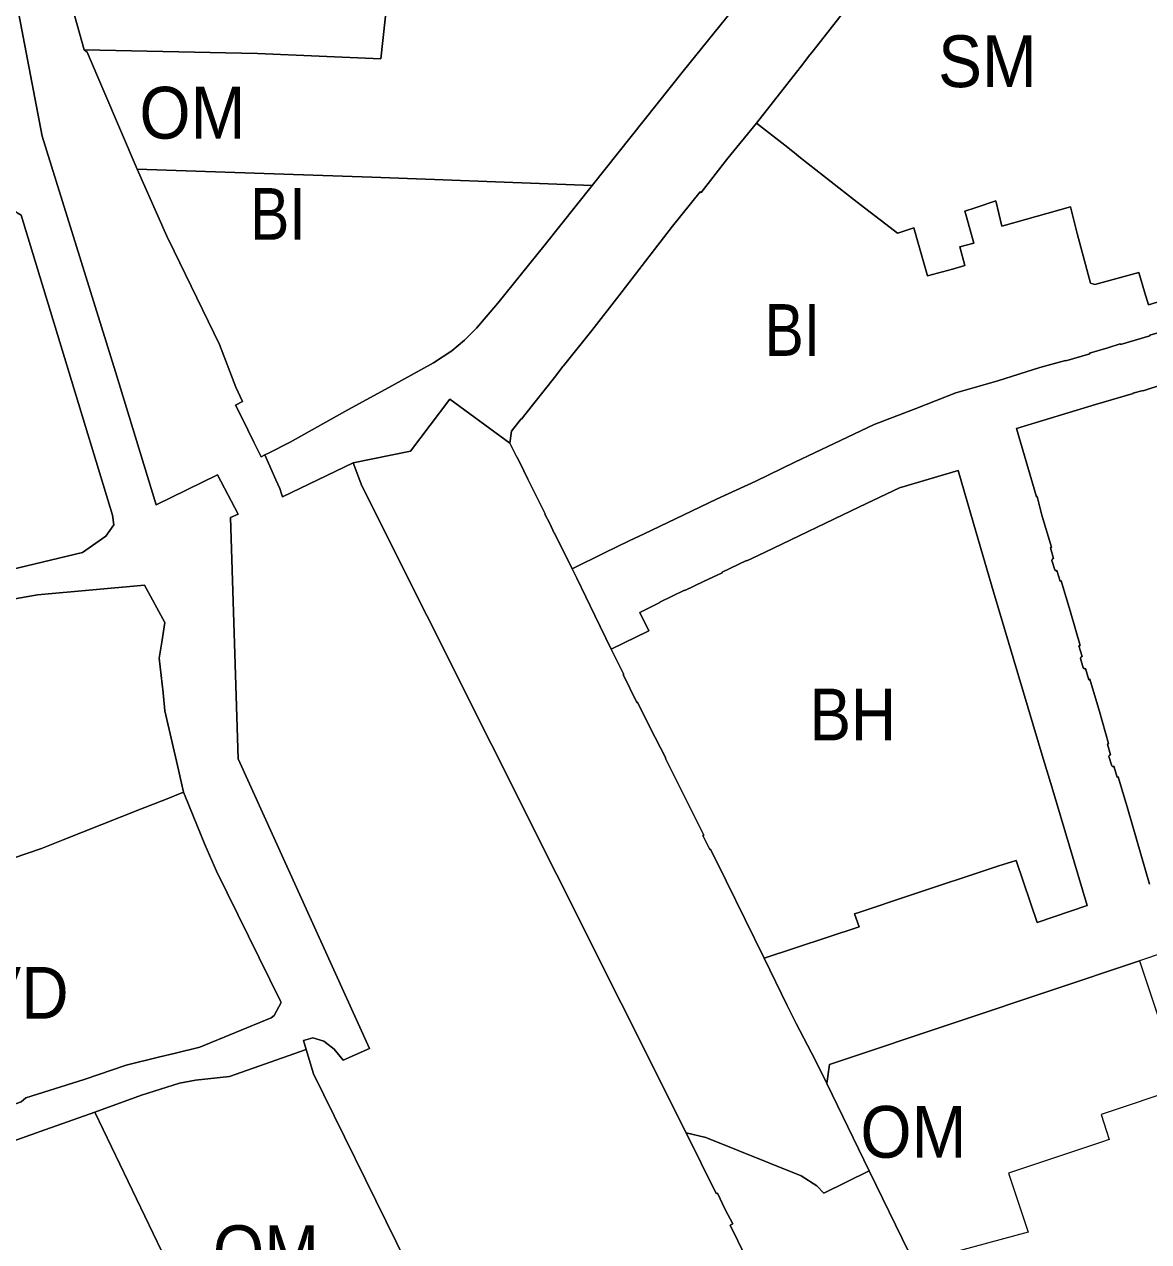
# Model space of a CAD drawing. Extents: x -650451 to -642268, y -1075216 to -1066610.
# Drawn here: x -647868.5 to -647608.2, y -1070794.3 to -1070512.4 of the extents above; entities that cross this region are included whole.
import ezdxf

# ---------------------------------------------------------------- set-up
doc = ezdxf.new("R2010")
doc.units = 0
doc.header["$LTSCALE"] = 4.8
for name, color, linetype, lineweight in [('1', 7, 'Continuous', 13), ('11', 7, 'Continuous', 13), ('12', 7, 'Continuous', 13), ('15', 7, 'Continuous', 13), ('18', 7, 'Continuous', 13), ('2', 7, 'Continuous', 13), ('24', 7, 'Continuous', 13), ('25', 7, 'Continuous', 13), ('35', 7, 'Continuous', 13)]:
    doc.layers.add(name, color=color, linetype=linetype, lineweight=lineweight)
doc.layers.add('62', color=7, linetype='Continuous')

msp = doc.modelspace()

# ---------------------------------------------------------------- linework, layer by layer
at = {"layer": '1'}
for points in [[(-647607.96, -1070711.55), (-647612.98, -1070694.17), (-647615.21, -1070686.65), (-647615.48, -1070686.75), (-647616.22, -1070684.23), (-647616.47, -1070684.33), (-647616.72, -1070684.14), (-647617.37, -1070681.97), (-647617.24, -1070681.65), (-647617.01, -1070681.56), (-647617.73, -1070679.09), (-647617.45, -1070678.98), (-647619.6, -1070671.54), (-647621.78, -1070664.08), (-647622.06, -1070664.18), (-647622.83, -1070661.6), (-647623.03, -1070661.67), (-647623.36, -1070661.41), (-647623.94, -1070659.3), (-647623.84, -1070658.92), (-647623.61, -1070658.84), (-647624.32, -1070656.37), (-647624.04, -1070656.27), (-647626.19, -1070648.79), (-647628.41, -1070641.25), (-647628.67, -1070641.34), (-647629.41, -1070638.87), (-647629.59, -1070638.94), (-647629.93, -1070638.72), (-647630.57, -1070636.58), (-647630.47, -1070636.18), (-647630.25, -1070636.1), (-647630.93, -1070633.62), (-647630.65, -1070633.51), (-647632.89, -1070626.04), (-647633.98, -1070621.78), (-647634.12, -1070621.83), (-647638.76, -1070605.98), (-647620.49, -1070600.48), (-647611.81, -1070597.91), (-647611.83, -1070597.85), (-647609.48, -1070597.18), (-647609.46, -1070597.25), (-647604.74, -1070595.77)], [(-647732.61, -1070657.08), (-647723.91, -1070652.88), (-647725.98, -1070648.59), (-647721.35, -1070646.32), (-647721.4, -1070646.19), (-647715.68, -1070643.41), (-647715.62, -1070643.56), (-647711.25, -1070641.47), (-647706.92, -1070639.43), (-647706.97, -1070639.28), (-647701.31, -1070636.54), (-647701.26, -1070636.68), (-647696.95, -1070634.64), (-647675.17, -1070624.15), (-647665.9, -1070619.71), (-647652.31, -1070615.72), (-647648.1, -1070630.11), (-647644.14, -1070643.84), (-647632.63, -1070682.45), (-647630.62, -1070688.97), (-647622.42, -1070716.46), (-647633.97, -1070720.39), (-647637.16, -1070711.08), (-647638.89, -1070706.02), (-647642.89, -1070707.32), (-647663.76, -1070714.27), (-647675.08, -1070718.03), (-647676.32, -1070718.44), (-647675.18, -1070721.4), (-647697.19, -1070728.71)], [(-647697.19, -1070728.71), (-647706.03, -1070710.73), (-647709.63, -1070703.43), (-647709.81, -1070703.52), (-647711.41, -1070700.27), (-647711.22, -1070700.17), (-647714.83, -1070692.9), (-647718.4, -1070685.67), (-647718.46, -1070685.698), (-647720.094, -1070682.395), (-647720.01, -1070682.36), (-647723.69, -1070675.2), (-647726.54, -1070669.36), (-647726.67, -1070669.43), (-647729.88, -1070663.01), (-647729.74, -1070662.95), (-647732.61, -1070657.08)], [(-647940.38, -1070810.06), (-647941.01, -1070809.16), (-647923.51, -1070797.95), (-647906.13, -1070787.1), (-647898.99, -1070783.35), (-647885.65, -1070776.94), (-647883.78, -1070776.11), (-647878.36, -1070773.89), (-647871.54, -1070771.23), (-647865.7, -1070769.15), (-647864.85, -1070768.85), (-647852.16, -1070764.35)], [(-647852.16, -1070764.35), (-647832.89, -1070804.46), (-647831.15, -1070808.09), (-647815.42, -1070840.8), (-647815.09, -1070841.49)]]:
    msp.add_lwpolyline(points, dxfattribs=at)
at = {"layer": '11'}
msp.add_lwpolyline([(-647879.89, -1070513.91), (-647874.57, -1070543.74), (-647874.57, -1070544.88), (-647875.18, -1070545.86), (-647875.88, -1070546.28), (-647875.79, -1070546.93), (-647875.64, -1070547.77), (-647874.97, -1070551.71), (-647874.48, -1070554.33), (-647872.39, -1070554.51), (-647871.15, -1070555.05), (-647870.17, -1070556.03), (-647869.25, -1070556.63), (-647848.14, -1070626.09), (-647847.8, -1070628.31), (-647849.67, -1070630.94), (-647855.03, -1070634.7), (-647869.87, -1070638.25), (-647907.21, -1070647.84), (-647941.33, -1070659.67), (-647955.81, -1070667.9), (-647961.11, -1070670.91)], dxfattribs=at)
at = {"layer": '12'}
for points in [[(-647854.68, -1070518.29), (-647814.55, -1070519.13), (-647785.99, -1070520.38), (-647781.43, -1070478.65)], [(-647781.43, -1070478.65), (-647696.44, -1070487.29), (-647695.82, -1070490.27), (-647694.91, -1070492.48), (-647693.13, -1070494.91), (-647715.98, -1070523.28), (-647737.05, -1070549.71)], [(-647842.39, -1070545.96), (-647853.97, -1070518.82), (-647854.68, -1070518.29)], [(-647737.05, -1070549.71), (-647757.4, -1070548.94), (-647773.54, -1070548.32), (-647788.08, -1070547.77), (-647842.39, -1070545.96)], [(-647682.67, -1070757.67), (-647682.08, -1070753.29), (-647651.82, -1070743.17), (-647610.33, -1070729.281)], [(-647610.33, -1070729.281), (-647600.53, -1070758.65), (-647619.2, -1070764.85), (-647617.36, -1070770.69), (-647619.12, -1070771.28), (-647640.66, -1070778.47), (-647636.12, -1070792.13), (-647654.89, -1070797.23), (-647662.26, -1070799.23)], [(-647852.16, -1070764.35), (-647841.37, -1070760.42), (-647832.6, -1070757.6), (-647828.92, -1070756.92), (-647821.05, -1070756.07), (-647803.27, -1070749.84)], [(-647803.27, -1070749.84), (-647801.54, -1070755.44), (-647782.32, -1070794.55), (-647764.84, -1070830.47), (-647765.72, -1070830.64)], [(-647662.26, -1070799.23), (-647663.71, -1070796.77), (-647672.865, -1070777.891), (-647682.67, -1070757.67)], [(-647815.09, -1070841.49), (-647815.42, -1070840.8), (-647831.15, -1070808.09), (-647832.89, -1070804.46), (-647852.16, -1070764.35)]]:
    msp.add_lwpolyline(points, dxfattribs=at)
at = {"layer": '15'}
for points in [[(-647884.92, -1070338.99), (-647886.21, -1070365.54), (-647887.07, -1070416.41), (-647878.96, -1070462.33), (-647864.39, -1070538.27), (-647847.43, -1070592.87), (-647838.01, -1070623.65), (-647823.823, -1070616.697), (-647819.04, -1070625.82), (-647820.78, -1070626.64), (-647818.97, -1070682.49), (-647788.61, -1070749.59), (-647794.72, -1070752.32), (-647796.81, -1070749.77), (-647799.17, -1070747.87), (-647801.72, -1070747.13), (-647803.86, -1070747.73), (-647803.27, -1070749.84)], [(-647622.98, -1070439.01), (-647623.27, -1070440.39), (-647624.25, -1070440.21), (-647627.38, -1070444.2), (-647627.26, -1070444.3), (-647636.05, -1070455.39), (-647636.18, -1070455.29), (-647639.17, -1070459.21), (-647641.31, -1070461.98), (-647654.26, -1070478.61), (-647664.91, -1070491.95), (-647674.88, -1070504.49), (-647685.86, -1070518.5), (-647686.94, -1070519.87), (-647688.05, -1070521.29), (-647699, -1070535.25)], [(-647737.05, -1070549.71), (-647715.98, -1070523.28), (-647693.13, -1070494.91), (-647694.91, -1070492.48), (-647695.82, -1070490.27), (-647696.44, -1070487.29), (-647781.43, -1070478.65)], [(-647961.11, -1070670.91), (-647955.81, -1070667.9), (-647941.33, -1070659.67), (-647907.21, -1070647.84), (-647869.87, -1070638.25), (-647855.03, -1070634.7), (-647849.67, -1070630.94), (-647847.8, -1070628.31), (-647848.14, -1070626.09), (-647869.25, -1070556.63), (-647870.17, -1070556.03), (-647871.15, -1070555.05), (-647872.39, -1070554.51), (-647874.48, -1070554.33), (-647874.97, -1070551.71), (-647875.64, -1070547.77), (-647875.79, -1070546.93), (-647875.88, -1070546.28), (-647875.18, -1070545.86), (-647874.57, -1070544.88), (-647874.57, -1070543.74), (-647879.89, -1070513.91)], [(-647699, -1070535.25), (-647705.6, -1070543.36), (-647711.81, -1070551.37), (-647712, -1070551.21), (-647718.41, -1070559.17), (-647724.69, -1070567.22), (-647730.85, -1070575.29), (-647737.13, -1070583.31), (-647743.65, -1070591.47), (-647743.8, -1070591.67), (-647745.76, -1070594.16), (-647752.62, -1070602.85), (-647753.39, -1070603.81), (-647753.47, -1070603.74), (-647755.74, -1070606.59), (-647756.13, -1070609.41)], [(-647812.82, -1070612.11), (-647812, -1070611.69), (-647807, -1070609.17), (-647794.31, -1070602.04), (-647783.46, -1070596.13), (-647773.75, -1070590.81), (-647769.52, -1070587.99), (-647766.59, -1070585.58), (-647763.83, -1070582.8), (-647758.9, -1070576.94), (-647747.95, -1070563.36), (-647737.05, -1070549.71)], [(-647741.7, -1070638.5), (-647734.17, -1070634.77), (-647728.44, -1070632.04), (-647725.01, -1070630.41), (-647717.77, -1070626.96), (-647708.23, -1070622.36), (-647699.17, -1070618.19), (-647690.11, -1070613.79), (-647680.98, -1070609.51), (-647671.77, -1070605.06), (-647662.28, -1070601.45), (-647652.86, -1070597.72), (-647643.11, -1070594.93), (-647633.4, -1070591.9), (-647627.42, -1070590.22), (-647627.38, -1070590.33), (-647621.83, -1070588.68), (-647621.89, -1070588.54), (-647617.66, -1070587.29), (-647614.79, -1070586.43), (-647614.73, -1070586.57), (-647607.88, -1070584.57), (-647607.93, -1070584.42), (-647601.55, -1070582.5)], [(-647604.74, -1070595.77), (-647609.46, -1070597.25), (-647609.48, -1070597.18), (-647611.83, -1070597.85), (-647611.81, -1070597.91), (-647620.49, -1070600.48), (-647638.76, -1070605.98), (-647634.12, -1070621.83), (-647633.98, -1070621.78), (-647632.89, -1070626.04), (-647630.65, -1070633.51), (-647630.93, -1070633.62), (-647630.25, -1070636.1), (-647630.47, -1070636.18), (-647630.57, -1070636.58), (-647629.93, -1070638.72), (-647629.59, -1070638.94), (-647629.41, -1070638.87), (-647628.67, -1070641.34), (-647628.41, -1070641.25), (-647626.19, -1070648.79), (-647624.04, -1070656.27), (-647624.32, -1070656.37), (-647623.61, -1070658.84), (-647623.84, -1070658.92), (-647623.94, -1070659.3), (-647623.36, -1070661.41), (-647623.03, -1070661.67), (-647622.83, -1070661.6), (-647622.06, -1070664.18), (-647621.78, -1070664.08), (-647619.6, -1070671.54), (-647617.45, -1070678.98), (-647617.73, -1070679.09), (-647617.01, -1070681.56), (-647617.24, -1070681.65), (-647617.37, -1070681.97), (-647616.72, -1070684.14), (-647616.47, -1070684.33), (-647616.22, -1070684.23), (-647615.48, -1070686.75), (-647615.21, -1070686.65), (-647612.98, -1070694.17), (-647607.96, -1070711.55)], [(-647756.13, -1070609.41), (-647769.961, -1070599.197), (-647779.08, -1070611.27), (-647792.4, -1070613.99)], [(-647792.4, -1070613.99), (-647808.77, -1070621.81), (-647808.99, -1070621.12), (-647809.39, -1070619.89), (-647810.28, -1070617.88), (-647812.82, -1070612.11)], [(-647697.19, -1070728.71), (-647675.18, -1070721.4), (-647676.32, -1070718.44), (-647675.08, -1070718.03), (-647663.76, -1070714.27), (-647642.89, -1070707.32), (-647638.89, -1070706.02), (-647637.16, -1070711.08), (-647633.97, -1070720.39), (-647622.42, -1070716.46), (-647630.62, -1070688.97), (-647632.63, -1070682.45), (-647644.14, -1070643.84), (-647648.1, -1070630.11), (-647652.31, -1070615.72), (-647665.9, -1070619.71), (-647675.17, -1070624.15), (-647696.95, -1070634.64), (-647701.26, -1070636.68), (-647701.31, -1070636.54), (-647706.97, -1070639.28), (-647706.92, -1070639.43), (-647711.25, -1070641.47), (-647715.62, -1070643.56), (-647715.68, -1070643.41), (-647721.4, -1070646.19), (-647721.35, -1070646.32), (-647725.98, -1070648.59), (-647723.91, -1070652.88), (-647732.61, -1070657.08)], [(-647732.61, -1070657.08), (-647736.4, -1070649.31), (-647740.59, -1070640.7), (-647741.7, -1070638.5)], [(-647831.69, -1070690.25), (-647832.86, -1070685.08), (-647835.96, -1070671.43), (-647836.41, -1070667.24), (-647837.27, -1070659.18), (-647836.7, -1070655.5), (-647835.98, -1070650.97), (-647840.71, -1070642.28), (-647865.49, -1070644.56), (-647897.91, -1070650.27), (-647905.7, -1070652.72), (-647914.94, -1070655.62), (-647928.03, -1070660.74), (-647939.82, -1070666.19), (-647938.2, -1070670.05)], [(-647925.06, -1070789.71), (-647914.43, -1070782.61), (-647894.71, -1070772.31), (-647886.51, -1070768.03), (-647869.29, -1070761.92), (-647868.14, -1070761.03), (-647854.65, -1070756.77), (-647844.91, -1070753.48), (-647837.11, -1070751.54), (-647833.82, -1070750.74), (-647827.9, -1070749.31), (-647811.35, -1070742.52), (-647810.66, -1070741.93), (-647809.02, -1070738.94), (-647809.17, -1070738.64), (-647824.01, -1070708.56), (-647826.73, -1070702.37), (-647831.31, -1070691.17), (-647831.69, -1070690.25)], [(-647583.221, -1070720.205), (-647583.22, -1070720.2), (-647593.6, -1070723.68), (-647610.33, -1070729.281)], [(-647682.67, -1070757.67), (-647685.41, -1070752.2), (-647689.79, -1070743.79), (-647691.89, -1070739.6), (-647697.19, -1070728.71)], [(-647610.33, -1070729.281), (-647651.82, -1070743.17), (-647682.08, -1070753.29), (-647682.67, -1070757.67)], [(-647803.27, -1070749.84), (-647821.05, -1070756.07), (-647828.92, -1070756.92), (-647832.6, -1070757.6), (-647841.37, -1070760.42), (-647852.16, -1070764.35)], [(-647852.16, -1070764.35), (-647864.85, -1070768.85), (-647865.7, -1070769.15), (-647871.54, -1070771.23), (-647878.36, -1070773.89), (-647883.78, -1070776.11), (-647885.65, -1070776.94), (-647898.99, -1070783.35), (-647906.13, -1070787.1), (-647923.51, -1070797.95), (-647941.01, -1070809.16), (-647940.38, -1070810.06)], [(-647715.3, -1070769.09), (-647710.72, -1070770.23), (-647688.68, -1070779.09), (-647684.98, -1070781.39), (-647683.41, -1070783.12), (-647672.865, -1070777.891)], [(-647539.817, -1071089.199), (-647553.4, -1071061.35), (-647565.56, -1071036.69), (-647567.83, -1071032.07), (-647572.64, -1071022.41), (-647638.54, -1070887.82), (-647649.83, -1070864.82), (-647660.03, -1070856.69), (-647681.06, -1070839.75), (-647687.12, -1070826.94), (-647686.2, -1070826.54), (-647689.08, -1070820.64), (-647689.95, -1070821.13), (-647693.96, -1070813.49), (-647694.09, -1070813.56), (-647701.41, -1070798.33), (-647701.32, -1070798.28), (-647701.56, -1070797.79), (-647705.06, -1070790.51), (-647704.498, -1070790.24), (-647706.21, -1070786.87), (-647708.04, -1070783.07), (-647708.31, -1070783.21), (-647715.3, -1070769.09)], [(-647672.865, -1070777.891), (-647663.71, -1070796.77), (-647662.26, -1070799.23), (-647647.571, -1070829.133)]]:
    msp.add_lwpolyline(points, dxfattribs=at)
at = {"layer": '18'}
for points in [[(-647699, -1070535.25), (-647688.05, -1070521.29), (-647686.94, -1070519.87), (-647685.86, -1070518.5), (-647674.88, -1070504.49), (-647664.91, -1070491.95), (-647654.26, -1070478.61), (-647641.31, -1070461.98), (-647639.17, -1070459.21), (-647636.18, -1070455.29), (-647636.05, -1070455.39), (-647627.26, -1070444.3), (-647627.38, -1070444.2), (-647624.25, -1070440.21), (-647623.27, -1070440.39), (-647622.98, -1070439.01)], [(-647603.47, -1070575.9), (-647608.26, -1070577.34), (-647609.15, -1070574.35), (-647610.49, -1070569.86), (-647620.65, -1070572.68), (-647621.64, -1070572.35), (-647624.71, -1070560.83), (-647626.31, -1070554.69), (-647642.21, -1070559.13), (-647643.6, -1070553.3), (-647648.39, -1070554.89), (-647650.76, -1070555.68), (-647650.54, -1070556.45), (-647648.63, -1070563.05), (-647651.9, -1070563.95), (-647650.72, -1070568.29), (-647653.61, -1070569.09), (-647659.39, -1070570.67), (-647661.38, -1070563.65), (-647662.54, -1070559.55), (-647665.58, -1070560.54), (-647666.37, -1070560.79), (-647669.06, -1070558.71), (-647673.96, -1070554.91), (-647676.35, -1070553.05), (-647688.77, -1070543.3), (-647690.2, -1070542.18), (-647692.46, -1070540.39), (-647699, -1070535.25)]]:
    msp.add_lwpolyline(points, dxfattribs=at)
at = {"layer": '2'}
for points in [[(-647854.68, -1070518.29), (-647859.18, -1070502.24), (-647865.59, -1070470.14)], [(-647781.43, -1070478.65), (-647785.99, -1070520.38), (-647814.55, -1070519.13), (-647854.68, -1070518.29)], [(-647756.13, -1070609.41), (-647755.74, -1070606.59), (-647753.47, -1070603.74), (-647753.39, -1070603.81), (-647752.62, -1070602.85), (-647745.76, -1070594.16), (-647743.8, -1070591.67), (-647743.65, -1070591.47), (-647737.13, -1070583.31), (-647730.85, -1070575.29), (-647724.69, -1070567.22), (-647718.41, -1070559.17), (-647712, -1070551.21), (-647711.81, -1070551.37), (-647705.6, -1070543.36), (-647699, -1070535.25)], [(-647699, -1070535.25), (-647692.46, -1070540.39), (-647690.2, -1070542.18), (-647688.77, -1070543.3), (-647676.35, -1070553.05), (-647673.96, -1070554.91), (-647669.06, -1070558.71), (-647666.37, -1070560.79), (-647665.58, -1070560.54), (-647662.54, -1070559.55), (-647661.38, -1070563.65), (-647659.39, -1070570.67), (-647653.61, -1070569.09), (-647650.72, -1070568.29), (-647651.9, -1070563.95), (-647648.63, -1070563.05), (-647650.54, -1070556.45), (-647650.76, -1070555.68), (-647648.39, -1070554.89), (-647643.6, -1070553.3), (-647642.21, -1070559.13), (-647626.31, -1070554.69), (-647624.71, -1070560.83), (-647621.64, -1070572.35), (-647620.65, -1070572.68), (-647610.49, -1070569.86), (-647609.15, -1070574.35), (-647608.26, -1070577.34), (-647603.47, -1070575.9)], [(-647842.39, -1070545.96), (-647788.08, -1070547.77), (-647773.54, -1070548.32), (-647757.4, -1070548.94), (-647737.05, -1070549.71)], [(-647812.82, -1070612.11), (-647813.71, -1070612.56), (-647815.39, -1070609.15), (-647818.19, -1070603.48), (-647819.61, -1070600.59), (-647817.98, -1070599.75), (-647819.55, -1070596.44), (-647823.34, -1070586.53), (-647833.81, -1070564.95), (-647835.51, -1070561.45), (-647842.39, -1070545.96)], [(-647737.05, -1070549.71), (-647747.95, -1070563.36), (-647758.9, -1070576.94), (-647763.83, -1070582.8), (-647766.59, -1070585.58), (-647769.52, -1070587.99), (-647773.75, -1070590.81), (-647783.46, -1070596.13), (-647794.31, -1070602.04), (-647807, -1070609.17), (-647812, -1070611.69), (-647812.82, -1070612.11)], [(-647601.55, -1070582.5), (-647607.93, -1070584.42), (-647607.88, -1070584.57), (-647614.73, -1070586.57), (-647614.79, -1070586.43), (-647617.66, -1070587.29), (-647621.89, -1070588.54), (-647621.83, -1070588.68), (-647627.38, -1070590.33), (-647627.42, -1070590.22), (-647633.4, -1070591.9), (-647643.11, -1070594.93), (-647652.86, -1070597.72), (-647662.28, -1070601.45), (-647671.77, -1070605.06), (-647680.98, -1070609.51), (-647690.11, -1070613.79), (-647699.17, -1070618.19), (-647708.23, -1070622.36), (-647717.77, -1070626.96), (-647725.01, -1070630.41), (-647728.44, -1070632.04), (-647734.17, -1070634.77), (-647741.7, -1070638.5)], [(-647741.7, -1070638.5), (-647745.75, -1070630.23), (-647745.84, -1070630.27), (-647746.82, -1070628.04), (-647747.99, -1070625.83), (-647747.9, -1070625.79), (-647751.91, -1070617.72), (-647751.96, -1070617.74), (-647752.9, -1070615.84), (-647752.85, -1070615.82), (-647754.41, -1070612.65), (-647754.49, -1070612.68), (-647756.13, -1070609.41)], [(-647938.2, -1070670.05), (-647939.82, -1070666.19), (-647928.03, -1070660.74), (-647914.94, -1070655.62), (-647905.7, -1070652.72), (-647897.91, -1070650.27), (-647865.49, -1070644.56), (-647840.71, -1070642.28), (-647835.98, -1070650.97), (-647836.7, -1070655.5), (-647837.27, -1070659.18), (-647836.41, -1070667.24), (-647835.96, -1070671.43), (-647832.86, -1070685.08), (-647831.69, -1070690.25)], [(-647831.69, -1070690.25), (-647835.87, -1070691.91), (-647841.59, -1070694.17), (-647859.53, -1070701.28), (-647864.53, -1070703.26), (-647883.85, -1070709.85), (-647896.03, -1070714.02), (-647907.68, -1070717.84), (-647920.01, -1070722.11)]]:
    msp.add_lwpolyline(points, dxfattribs=at)
at = {"layer": '24'}
for points in [[(-647792.4, -1070613.99), (-647779.08, -1070611.27), (-647769.961, -1070599.197), (-647756.13, -1070609.41)], [(-647756.13, -1070609.41), (-647754.49, -1070612.68), (-647754.41, -1070612.65), (-647752.85, -1070615.82), (-647752.9, -1070615.84), (-647751.96, -1070617.74), (-647751.91, -1070617.72), (-647747.9, -1070625.79), (-647747.99, -1070625.83), (-647746.82, -1070628.04), (-647745.84, -1070630.27), (-647745.75, -1070630.23), (-647741.7, -1070638.5)], [(-647715.3, -1070769.09), (-647790.4, -1070619.27), (-647792.4, -1070613.99)], [(-647741.7, -1070638.5), (-647740.59, -1070640.7), (-647736.4, -1070649.31), (-647732.61, -1070657.08)], [(-647732.61, -1070657.08), (-647729.74, -1070662.95), (-647729.88, -1070663.01), (-647726.67, -1070669.43), (-647726.54, -1070669.36), (-647723.69, -1070675.2), (-647720.01, -1070682.36), (-647720.094, -1070682.395), (-647718.46, -1070685.698), (-647718.4, -1070685.67), (-647714.83, -1070692.9), (-647711.22, -1070700.17), (-647711.41, -1070700.27), (-647709.81, -1070703.52), (-647709.63, -1070703.43), (-647706.03, -1070710.73), (-647697.19, -1070728.71)], [(-647697.19, -1070728.71), (-647691.89, -1070739.6), (-647689.79, -1070743.79), (-647685.41, -1070752.2), (-647682.67, -1070757.67), (-647672.865, -1070777.891)], [(-647672.865, -1070777.891), (-647683.41, -1070783.12), (-647684.98, -1070781.39), (-647688.68, -1070779.09), (-647710.72, -1070770.23), (-647715.3, -1070769.09)]]:
    msp.add_lwpolyline(points, dxfattribs=at)
at = {"layer": '25'}
for points in [[(-647803.27, -1070749.84), (-647803.86, -1070747.73), (-647801.72, -1070747.13), (-647799.17, -1070747.87), (-647796.81, -1070749.77), (-647794.72, -1070752.32), (-647788.61, -1070749.59), (-647818.97, -1070682.49), (-647820.78, -1070626.64), (-647819.04, -1070625.82), (-647823.823, -1070616.697), (-647838.01, -1070623.65), (-647847.43, -1070592.87), (-647864.39, -1070538.27), (-647878.96, -1070462.33), (-647887.07, -1070416.41), (-647886.21, -1070365.54), (-647884.92, -1070338.99)], [(-647865.59, -1070470.14), (-647859.18, -1070502.24), (-647854.68, -1070518.29)], [(-647854.68, -1070518.29), (-647853.97, -1070518.82), (-647842.39, -1070545.96)], [(-647842.39, -1070545.96), (-647835.51, -1070561.45), (-647833.81, -1070564.95), (-647823.34, -1070586.53), (-647819.55, -1070596.44), (-647817.98, -1070599.75), (-647819.61, -1070600.59), (-647818.19, -1070603.48), (-647815.39, -1070609.15), (-647813.71, -1070612.56), (-647812.82, -1070612.11)], [(-647812.82, -1070612.11), (-647810.28, -1070617.88), (-647809.39, -1070619.89), (-647808.99, -1070621.12), (-647808.77, -1070621.81), (-647792.4, -1070613.99)], [(-647792.4, -1070613.99), (-647790.4, -1070619.27), (-647715.3, -1070769.09)], [(-647764.84, -1070830.47), (-647782.32, -1070794.55), (-647801.54, -1070755.44), (-647803.27, -1070749.84)], [(-647715.3, -1070769.09), (-647708.31, -1070783.21), (-647708.04, -1070783.07), (-647706.21, -1070786.87), (-647704.498, -1070790.24), (-647705.06, -1070790.51), (-647701.56, -1070797.79), (-647701.32, -1070798.28), (-647701.41, -1070798.33), (-647694.09, -1070813.56), (-647693.96, -1070813.49), (-647689.95, -1070821.13), (-647689.08, -1070820.64), (-647686.2, -1070826.54), (-647687.12, -1070826.94), (-647681.06, -1070839.75), (-647660.03, -1070856.69), (-647649.83, -1070864.82), (-647638.54, -1070887.82), (-647572.64, -1071022.41), (-647567.83, -1071032.07), (-647565.56, -1071036.69), (-647553.4, -1071061.35), (-647539.817, -1071089.199)]]:
    msp.add_lwpolyline(points, dxfattribs=at)
at = {"layer": '35'}
for points in [[(-647831.69, -1070690.25), (-647831.31, -1070691.17), (-647826.73, -1070702.37), (-647824.01, -1070708.56), (-647809.17, -1070738.64), (-647809.02, -1070738.94), (-647810.66, -1070741.93), (-647811.35, -1070742.52), (-647827.9, -1070749.31), (-647833.82, -1070750.74), (-647837.11, -1070751.54), (-647844.91, -1070753.48), (-647854.65, -1070756.77), (-647868.14, -1070761.03), (-647869.29, -1070761.92), (-647886.51, -1070768.03), (-647894.71, -1070772.31), (-647914.43, -1070782.61), (-647925.06, -1070789.71)], [(-647920.01, -1070722.11), (-647907.68, -1070717.84), (-647896.03, -1070714.02), (-647883.85, -1070709.85), (-647864.53, -1070703.26), (-647859.53, -1070701.28), (-647841.59, -1070694.17), (-647835.87, -1070691.91), (-647831.69, -1070690.25)]]:
    msp.add_lwpolyline(points, dxfattribs=at)

# ---------------------------------------------------------------- texts
at = {"layer": '62'}
for s, width, p in [('SM', 0.95, (-647656.948, -1070526.948)), ('OM', 0.95, (-647841.878, -1070538.872)), ('BI', 0.85, (-647816.248, -1070562.307)), ('BI', 0.85, (-647697.133, -1070589.194)), ('BH', 0.9, (-647686.734, -1070678.237)), ('VD', 0.95, (-647879.427, -1070742.698)), ('OM', 0.95, (-647674.932, -1070774.894)), ('OM', 0.95, (-647824.844, -1070802.545))]:
    msp.add_text(s, height=12, dxfattribs=dict(at, width=width)).set_placement(p)

doc.saveas('drawing.dxf')
